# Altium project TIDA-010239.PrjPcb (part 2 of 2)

## Sheet TIDA-010239_Relay_DRV.SchDoc
size 431 x 279 mm; Date: Not shown in title block; ApprovedBy: Not shown in title block; CheckedBy: Not shown in title block; Author: Not shown in title block; CompanyName: Not shown in title block; Engineer: Not shown in title block; Organization: Not shown in title block; Address1: Not shown in title block; Address2: Not shown in title block; Address3: Not shown in title block; Address4: Not shown in title block; DocumentNumber: 1; Revision: Use project parameter SCH_Rev; SheetNumber: 4; SheetTotal: 9; PageSetup: Record=PageOptions¦CenterHorizontal=True¦CenterVertical=True¦PrintScale=1.00¦XCorrection=1.00¦YCorrection=1.00¦PrintKind=0¦BorderSize=5000000¦LeftOffset=0¦BottomOffset=0¦Orientation=2¦PaperLength=1000¦PaperWidth=1000¦Scale=100¦PaperSource=15¦PrintQuality=600¦MediaType=1¦DitherType=10¦PaperKind=Letter¦PrintScaleMode=1
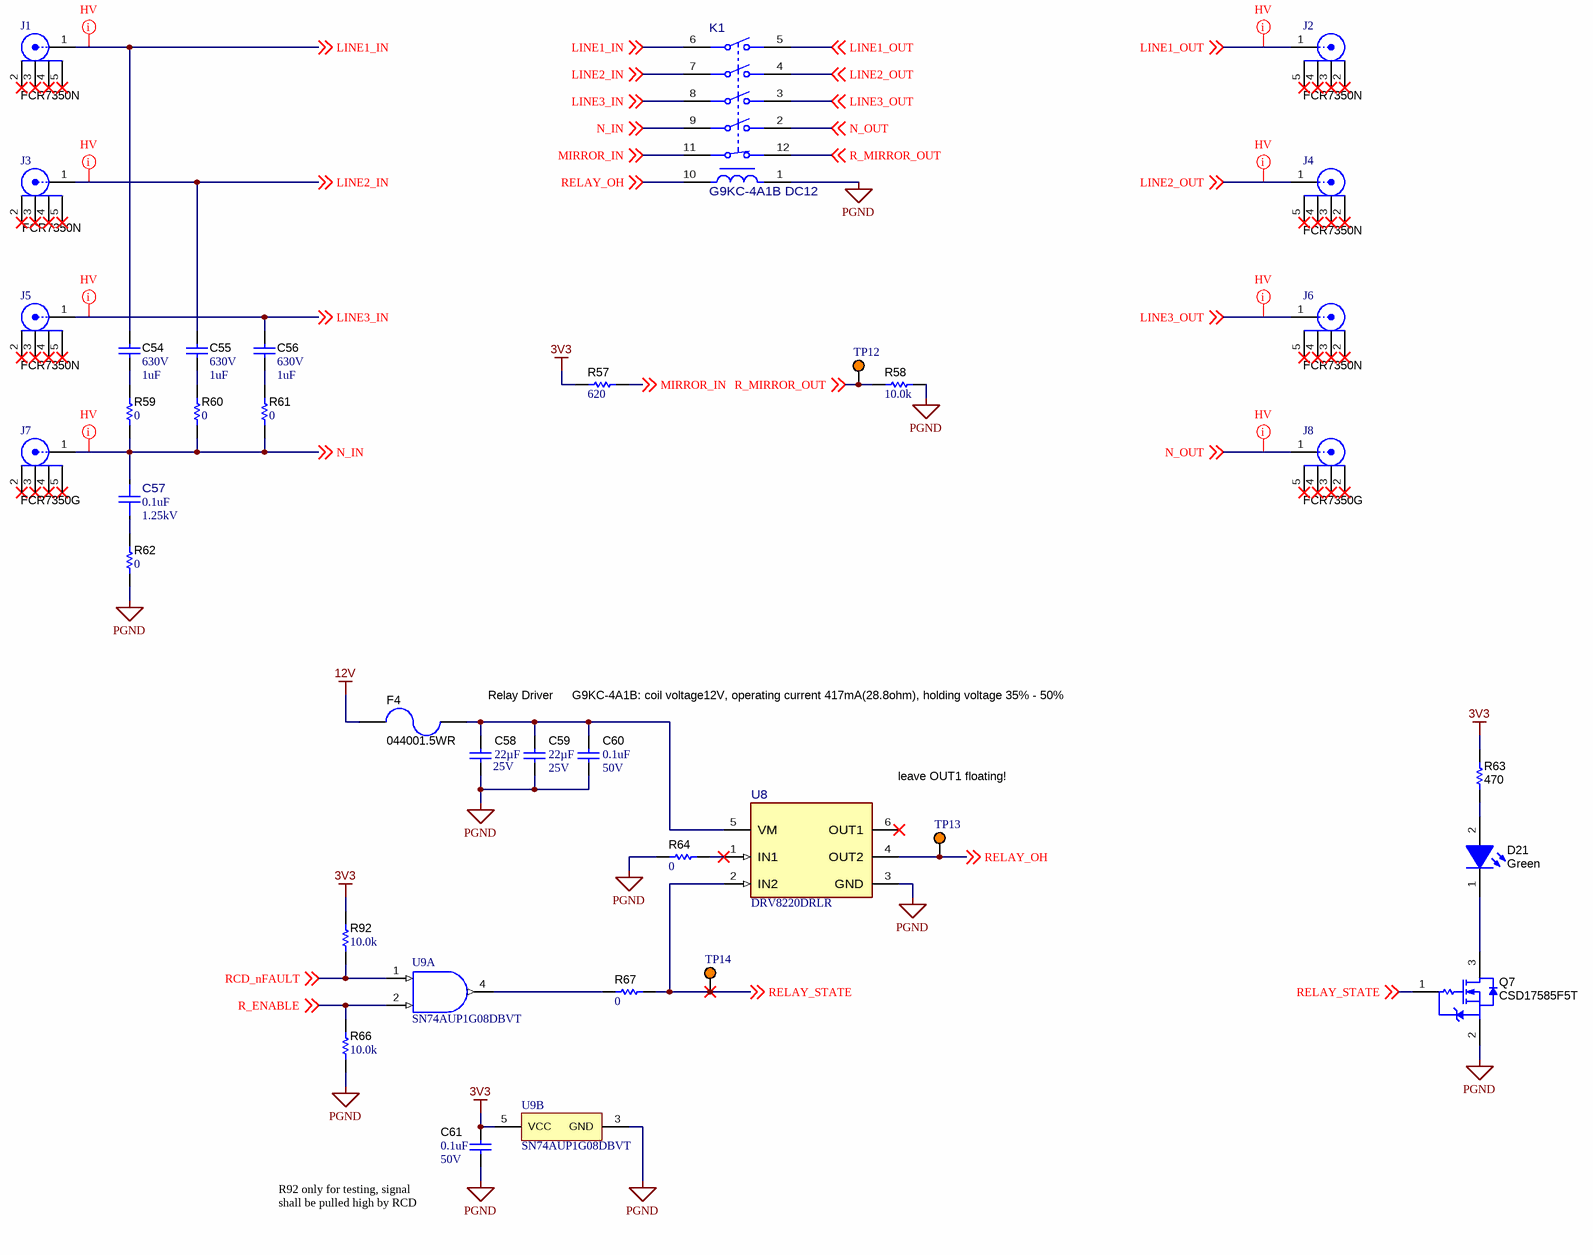
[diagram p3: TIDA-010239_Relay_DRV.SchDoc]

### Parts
C54  VDC_V: 630V  ValueDisplayed: 1uF  [B32923_20.5mm]  (hidden comment: B32923C3105M)
C55  VDC_V: 630V  ValueDisplayed: 1uF  [B32923_20.5mm]  (hidden comment: B32923C3105M)
C56  VDC_V: 630V  ValueDisplayed: 1uF  [B32923_20.5mm]  (hidden comment: B32923C3105M)
C57  ValueDisplayed: 0.1uF  VDC_V: 1.25kV  [FP-PHE850ED6100MD18R06L2_RADIAL-MFG]  (hidden comment: PHE850ED6100MD18R06L2)
C58  VDC_V: 25V  ValueDisplayed: 22µF  [1210_270]  (hidden comment: CC1210KKX7R8BB226)
C59  VDC_V: 25V  ValueDisplayed: 22µF  [1210_270]  (hidden comment: CC1210KKX7R8BB226)
C60  value 0.1uF  VDC_V: 50V  [0603]  (hidden comment: C1608X7R1H104K080AA)
C61  value 0.1uF  VDC_V: 50V  [0603]  (hidden comment: C1608X7R1H104K080AA)
D21  value Green  [WL-SMCW_GREEN]  (hidden comment: 150060GS75000)
F4  044001.5WR  [1206]
J1  FCR7350N  [FP-FCR7350N_CONN_BANANA_JACK-MFG]
J2  FCR7350N  [FP-FCR7350N_CONN_BANANA_JACK-MFG]
J3  FCR7350N  [FP-FCR7350N_CONN_BANANA_JACK-MFG]
J4  FCR7350N  [FP-FCR7350N_CONN_BANANA_JACK-MFG]
J5  FCR7350N  [FP-FCR7350N_CONN_BANANA_JACK-MFG]
J6  FCR7350N  [FP-FCR7350N_CONN_BANANA_JACK-MFG]
J7  FCR7350G  [FP-FCR7350G_CONN_BANANA_JACK-MFG]
J8  FCR7350G  [FP-FCR7350G_CONN_BANANA_JACK-MFG]
K1  G9KC-4A1B DC12  [FP-G9KC-4A1B DC12_PTH_RELAY_58MM0_35MM0-MFG]
Q7  CSD17585F5T  [YJK0003A]
R57  ValueDisplayed: 620  [0603]  (hidden comment: RC0603FR-07620RL)
R58  ValueDisplayed: 10.0k  [0603]  (hidden comment: RC0603FR-0710KL)
R59  ValueDisplayed: 0  [1206]  (hidden comment: RC1206JR-070RL)
R60  ValueDisplayed: 0  [1206]  (hidden comment: RC1206JR-070RL)
R61  ValueDisplayed: 0  [1206]  (hidden comment: RC1206JR-070RL)
R62  ValueDisplayed: 0  [1206]  (hidden comment: RC1206JR-070RL)
R63  ValueDisplayed: 470  [0402]  (hidden comment: RC0402FR-07470RL)
R64  ValueDisplayed: 0  [0603]  (hidden comment: RCS06030000Z0EA)
R66  ValueDisplayed: 10.0k  [0603]  (hidden comment: RC0603FR-0710KL)
R67  ValueDisplayed: 0  [0603]  (hidden comment: RCS06030000Z0EA)
R92  ValueDisplayed: 10.0k  [0603]  (hidden comment: RC0603FR-0710KL)
TP12  5003  [Keystone5003]  (value not drawn)
TP13  5003  [Keystone5003]  (value not drawn)
TP14  5003  [Keystone5003]  (value not drawn)
U8  DRV8220DRLR  [DRL0006A-MFG]
U9  SN74AUP1G08DBVT  [DBV0005A_N]  (parts A,B of 2)

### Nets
3V3: C61.1 R57.1 R63.2 R92.2 U9.5(VCC)
12V: F4.2
PGND: C58.1 C59.1 C60.2 C61.2 K1.1 Q7.2(S) R58.2 R62.1 R64.2 R66.1 U8.3(GND) U9.3(GND)
LINE1_IN: C54.1 J1.1 K1.6 ; off-sheet LINE1_IN
LINE1_OUT: J2.1 K1.5 ; off-sheet LINE1_OUT
LINE2_IN: C55.1 J3.1 K1.7 ; off-sheet LINE2_IN
LINE2_OUT: J4.1 K1.4 ; off-sheet LINE2_OUT
LINE3_IN: C56.1 J5.1 K1.8 ; off-sheet LINE3_IN
LINE3_OUT: J6.1 K1.3 ; off-sheet LINE3_OUT
MIRROR_IN: K1.11 R57.2 ; off-sheet MIRROR_IN
N_IN: C57.2 J7.1 K1.9 R59.1 R60.1 R61.1 ; off-sheet N_IN
N_OUT: J8.1 K1.2 ; off-sheet N_OUT
R_ENABLE: R66.2 U9.2(B) ; off-sheet R_ENABLE
R_MIRROR_OUT: K1.12 R58.1 TP12.1 ; off-sheet R_MIRROR_OUT
RCD_nFAULT: R92.1 U9.1(A) ; off-sheet RCD_nFAULT
RELAY_OH: K1.10 TP13.1 U8.4(OUT2) ; off-sheet RELAY_OH
RELAY_STATE: Q7.1(G) R67.2 TP14.1 U8.2(IN2) ; off-sheet RELAY_STATE
NetC54_2: C54.2 R59.2
NetC55_2: C55.2 R60.2
NetC56_2: C56.2 R61.2
NetC57_1: C57.1 R62.2
NetC58_2: C58.2 C59.2 C60.1 F4.1 U8.5(VM)
NetD21_1: D21.1(K) Q7.3(D)
NetD21_2: D21.2(A) R63.1
NetR64_1: R64.1 U8.1(IN1)
NetR67_1: R67.1 U9.4(Y)

Not connected (* = marked no-connect by the designer): J1 2* 3* 4* 5*; J2 2* 3* 4* 5*; J3 2* 3* 4* 5*; J4 2* 3* 4* 5*; J5 2* 3* 4* 5*; J6 2* 3* 4* 5*; J7 2* 3* 4* 5*; J8 2* 3* 4* 5*; U8 6(OUT1)*

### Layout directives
net class HV: LINE1_IN, LINE1_OUT, LINE2_IN, LINE2_OUT, LINE3_IN, LINE3_OUT, N_IN, N_OUT

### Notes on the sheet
- Relay Driver
- G9KC-4A1B: coil voltage12V, operating current 417mA(28.8ohm), holding voltage 35% - 50%
- leave OUT1 floating!
- R92 only for testing, signal shall be pulled high by RCD

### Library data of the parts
C54-C56 = CMP-0012419-3: CAP, Film, 1 uF, 630 V, +/- 20%, 0.018 ohm, TH; Manufacturer: TDK; ESR_ohm: 18m; Polarized: N; SizeAreaWB_mm2: 370.5; Value: 1uF; TaMax_C: 110°C; SizeZ_mm: 20.5; SizeX_mm: 11; SizeY_mm: 26.5; SizeArea_mm2: 291.5; Cap_F: 1µF; IRMS_A: 97mA; AEC Category: Q200
C57 = CMP-0040174-1: Cap Film Suppression Y2 0.1uF 1250VDC/300VAC PP 20% (26 X 10.5 X 19mm) Radial 22.5mm 110C Tray; Manufacturer: Kemet; AEC Qualified: No; Cap_F: 100nF; VAC: 300V; Value: 100nF
C58 C59 = CMP-0082267-1: CAP, CERM, 22 µF, 25 V,+/- 10%, X7R, 1210; Manufacturer: Yageo; TaMin_C: -55°C; ESR_ohm: 1m; Polarized: N; SizeAreaWB_mm2: 14.7; Value1: 0.001 ohm; U/M: EA; Value: 22uF; TaMax_C: 125°C; SizeZ_mm: 2.7; SizeX_mm: 3.2; SizeY_mm: 2.5; Cap_Case: 1210; SizeArea_mm2: 8; AEC Category: Q200
C60 C61 = CMP-0007044-5: CAP, CERM, 0.1 uF, 50 V, +/- 10%, X7R, 0603; Manufacturer: TDK; TaMin_C: -55°C; ESR_ohm: 29.6m; Polarized: N; SizeAreaWB_mm2: 4.68; Value1: 0.0296 ohm; U/M: EA; TaMax_C: 125°C; SizeZ_mm: 1; SizeX_mm: 1.6; SizeY_mm: 0.8; SizeArea_mm2: 1.28; Cap_F: 100nF; IRMS_A: 971.99mA; AEC Category: Q200
D21 = CMP-0002905-2: LED, Green, SMD; Manufacturer: Wurth Elektronik; Type: InGaN; Vf_V: 3.2V; Io_A: 20mA; Tjmax_C: 85°C; Value1: W; Angle: 140
F4 = CMP-0003461-2: Fuse, 1.5 A, 50VAC/VDC, SMD; Manufacturer: Littelfuse; Irating_A: 1.5A; SizeAreaWB_mm2: 10.92; Interrupt_AC: 50A; VAC_V: 50V; SizeZ_mm: 1.35; SizeX_mm: 3.2; SizeY_mm: 1.6; SizeArea_mm2: 5.12; Rtyp_Ohm: 0.1759; MeltingTyp: 0.50652
J1-J6 = CMP-0098296-2: Banana Test Connector, Socket, PCB Mount, 24 A, 1 kV, Gold Plated Contacts, Brown; Manufacturer: CLIFF Electronic Components; Current_A: 24A; Voltage_V: 1kV; AEC Qualified: No; Conn Orientation: Right Angle; Is Female: yes; SizeZ_mm: 11.6mm; Standoff Height: 0.7mm
J7 J8 = CMP-0098294-2: Banana Test Connector, Socket, PCB Mount, 24 A, 1 kV, Gold Plated Contacts, Green; Manufacturer: CLIFF Electronic Components; Current_A: 24A; Voltage_V: 1kV; AEC Qualified: No; Conn Orientation: Right Angle; SizeZ_mm: 11.6mm; Standoff Height: 0.7mm
K1 = CMP-0127083-1: General Purpose Relay 5PST-4NO/1NC (4 Form A, 1 Form B) 12VDC Coil Through Hole; Manufacturer: Omron; Coil Current_A: 417mA; Coil Power_W: 5W; Coil Type: Non-Latching; Coil Voltage_VDC: 12V; Contact Form: 5PST-4NO-1NC; Contact Rating_A: 40A; SizeZ_mm: 47.5mm; AEC Qualified: No; Coil Resistance: 28.8Ω; TaMax_C: +85°C; TaMin_C: -40°C
Q7 = CMP-0067551-1: MOSFET, N-CH, 30 V, 5.9 A, YJK0003A (PICOSTAR-3); Alternate Manufacturer: None; Manufacturer: Texas Instruments; Rdson45_ohm: 0.033; QgTyp_nC: 1.9; SizeAreaWB_mm2: 4.3077; Vgs_V: 20V; Value1: 0.033 ohm; VdsMax_V: 30V; U/M: EA; Value: 30V; IdsMax_A: 5.9A; SizeZ_mm: 0.35; SizeX_mm: 1.49; SizeY_mm: 0.73; Value2: 1.9 nC; SizeArea_mm2: 1.0877; ChType: N; AEC Category: Q101
R57 = CMP-0023219-5: RES, 620, 1%, 0.1 W, 0603; Manufacturer: Yageo; Power_W: 100mW; TempCo: 100 ppm/C; Value_Code: 620R; Value: 620; SizeX_mm: 1.6; SizeY_mm: 0.8; SizeZ_mm: 1; Value2: 0.1W; SizeArea_mm2: 1.28; AEC Qualified: N; VDC_V: 75V; AEC Category: Q200; SizeAreaWB_mm2: 4.68
R58 R66 R92 = CMP-0022746-5: RES, 10.0 k, 1%, 0.1 W, 0603; Manufacturer: Yageo; Power_W: 100mW; TempCo: 100 ppm/C; Value_Code: 10k0; Value: 10.0k; EIA_Code: E96; Res_ohm: 10k; SizeX_mm: 1.6; SizeY_mm: 0.8; SizeZ_mm: 1; Value2: 0.1W; SizeArea_mm2: 1.28; AEC Qualified: N; VDC_V: 75V; AEC Category: Q200; SizeAreaWB_mm2: 4.68
R59-R62 = CMP-0018759-2: RES, 0, 5%, 0.25 W, 1206; Manufacturer: Yageo America; Power_W: 250mW; TempCo: 200 ppm/C; Value_Code: 0000; U/M: EA; Value: 0; EIA_Code: E24; SizeX_mm: 3.2; SizeY_mm: 1.6; SizeZ_mm: 1.35; Value2: 0.25W; SizeArea_mm2: 5.12; VDC_V: 200V; AEC Category: Q200
R63 = CMP-0026736-1: RES, 470, 1%, 0.063 W, 0402; Manufacturer: Yageo America; Power_W: 63mW; TempCo: 100 ppm/C; Value_Code: 470R; U/M: EA; Value: 470; SizeX_mm: 1; SizeY_mm: 0.5; SizeZ_mm: 0.6; Value2: 0.063W; AEC Qualified: N; VDC_V: 50V; AEC Category: Q200
R64 R67 = CMP-0081973-1: RES, 0, 0%, 0.25 W, AEC-Q200 Grade 0, 0603; Manufacturer: Vishay-Dale; SizeAreaWB_mm2: 4.68; SizeArea_mm2: 1.28; AEC Qualified: Y; AEC Category: Q200; Value: 0; SizeZ_mm: 1; SizeY_mm: 0.8; Power_W: 250mW; Value2: 0.25W; SizeX_mm: 1.6
TP12-TP14 = CMP-0055140-2: Test Point, Miniature, Orange, TH; Manufacturer: Keystone Electronics; CNHeader: FALSE; Green_Lifecycle: Active; Green_REACh: Passed; ContactFinish: Silver; CT: TRUE
U8 = CMP-0090278-3: 18V, 1A H-bridge motor driver, PWM, PH/EN, ½ bridge control, with low power sleep mode; Manufacturer: Texas Instruments; Standoff Height: 0mm; TaMax_C: +125°C; Number Of Outputs: 2; AEC Qualified: No; TJmax_C: +150°C; SizeZ_mm: 0.6mm; AEC Category: Q200; TaMin_C: -40°C; Switching Frequency: 100kHz; Min Supply Voltage: 4.5V; Motor Type: Brushed; CompType: IC
U9 = CMP-0051576-2: Low-Power Single 2-Input Positive-AND Gate, DBV0005A (SOT-23-5); Manufacturer: Texas Instruments; 3-State Output: No; Output Type: CMOS; F @ Nom Voltage(Max)(Mhz): 100; Rating: Catalog; Voltage(Nom)(V): 0.8,1.2,1.5,1.8,2.5,3.3; Logic: True; Output Drive (IOL/IOH)(Max)(mA): 20/-20; tpd @ Nom Voltage(Max)(ns): 32.8,20.9,14.2,11,7.6,6.2; Bits(#): 1; ICC @ Nom Voltage(Max)(mA): 0.0009; Gate Type: AND; VCC(Max)(V): 3.6; VCC(Min)(V): 0.8; AEC Category: Q200; AEC Qualified: N; CompType: IC; SizeAreaWB_mm2: 14.82; SizeArea_mm2: 8.12; SizeX_mm: 2.8; SizeY_mm: 2.9; SizeZ_mm: 1.45

## Sheet TIDA-010239_Weld_Detection.SchDoc
size 431 x 279 mm; Date: Not shown in title block; ApprovedBy: Not shown in title block; CheckedBy: Not shown in title block; Author: Not shown in title block; CompanyName: Not shown in title block; Engineer: Not shown in title block; Organization: Not shown in title block; Address1: Not shown in title block; Address2: Not shown in title block; Address3: Not shown in title block; Address4: Not shown in title block; DocumentNumber: 1; Revision: Use project parameter SCH_Rev; SheetNumber: 5; SheetTotal: 9; PageSetup: Record=PageOptions¦CenterHorizontal=True¦CenterVertical=True¦PrintScale=1.00¦XCorrection=1.00¦YCorrection=1.00¦PrintKind=0¦BorderSize=5000000¦LeftOffset=0¦BottomOffset=0¦Orientation=2¦PaperLength=1000¦PaperWidth=1000¦Scale=100¦PaperSource=15¦PrintQuality=600¦MediaType=1¦DitherType=10¦PaperKind=Letter¦PrintScaleMode=1
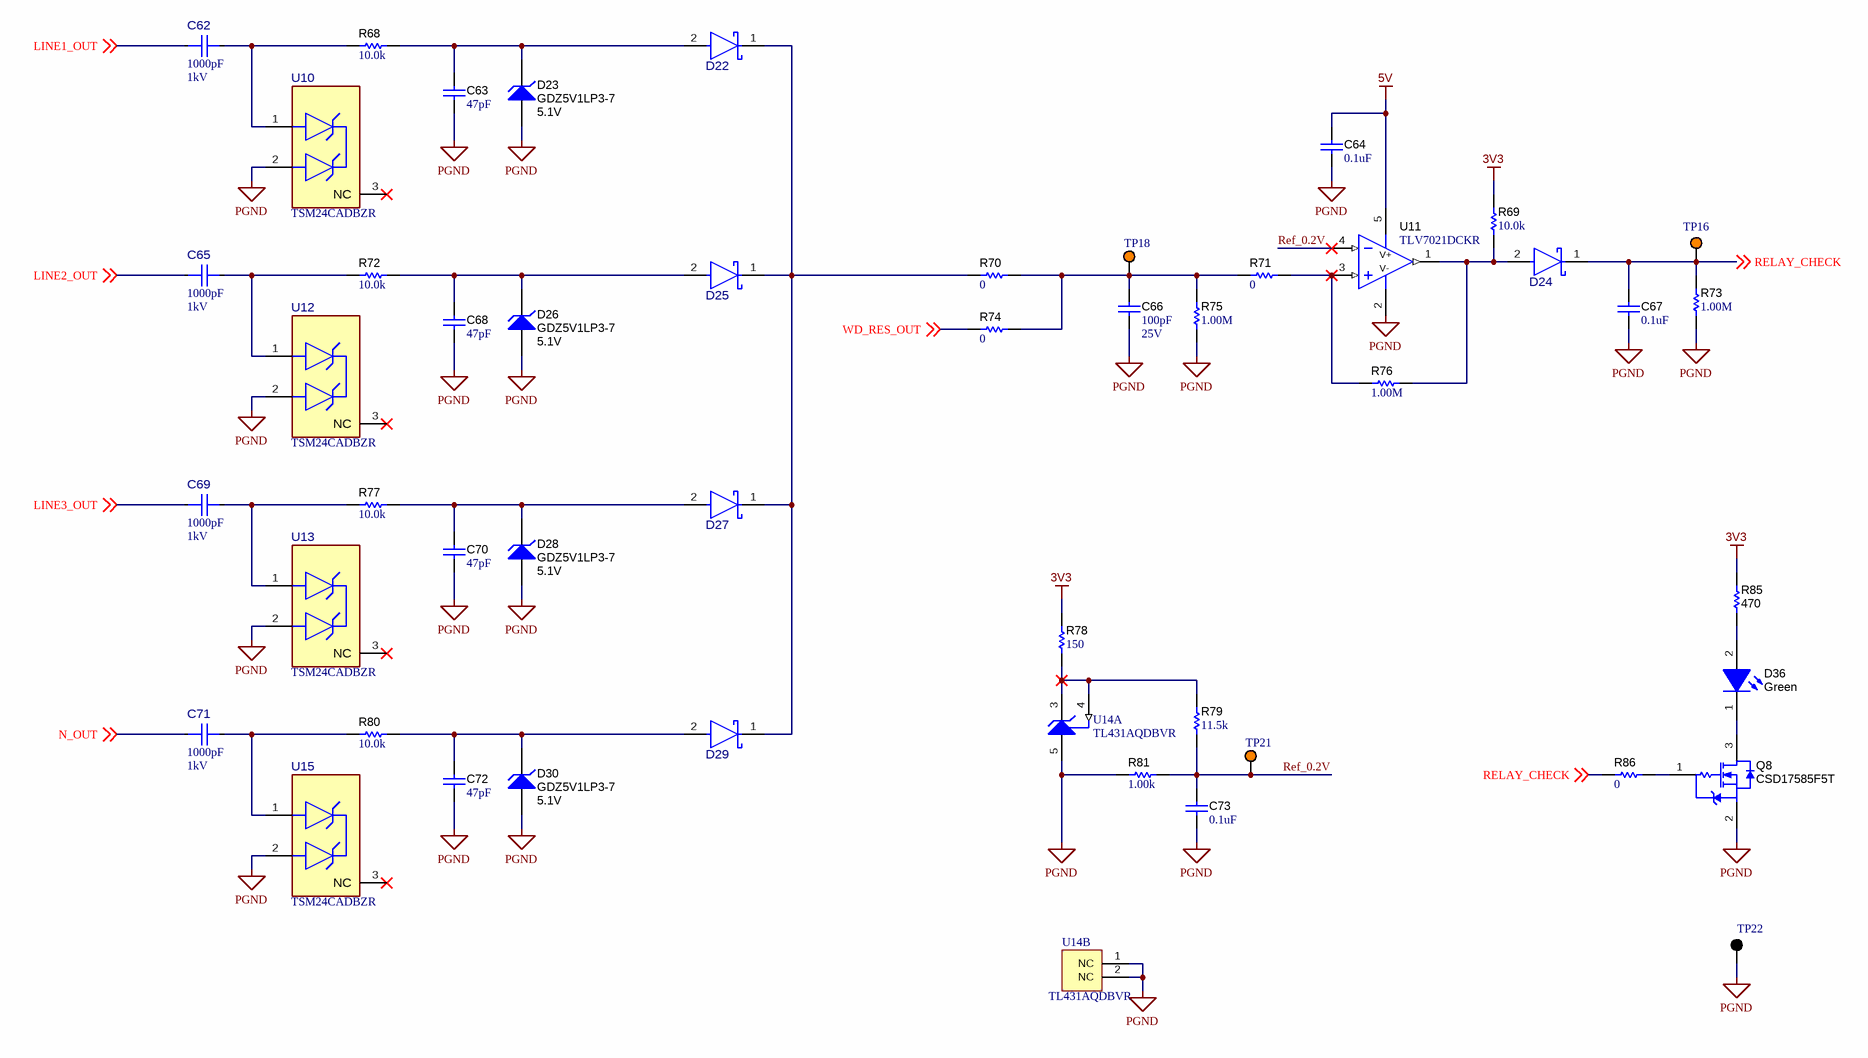
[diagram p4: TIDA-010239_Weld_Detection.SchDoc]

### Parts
C62  ValueDisplayed: 1000pF  VDC_V: 1kV  [FP-VY2102M29Y5US6TV7_RADIAL-MFG]  (hidden comment: VY2102M29Y5US6TV7)
C63  ValueDisplayed: 47pF  [0603]  (hidden comment: C0603C470J1GACAUTO)
C64  value 0.1uF  [0603]  (hidden comment: C1608X7R1H104K080AA)
C65  ValueDisplayed: 1000pF  VDC_V: 1kV  [FP-VY2102M29Y5US6TV7_RADIAL-MFG]  (hidden comment: VY2102M29Y5US6TV7)
C66  Cap_F: 100pF  VDC_V: 25V  [0603S]  (hidden comment: 06033C101KAT2A)
C67  value 0.1uF  [0603]  (hidden comment: C1608X7R1H104K080AA)
C68  ValueDisplayed: 47pF  [0603]  (hidden comment: C0603C470J1GACAUTO)
C69  ValueDisplayed: 1000pF  VDC_V: 1kV  [FP-VY2102M29Y5US6TV7_RADIAL-MFG]  (hidden comment: VY2102M29Y5US6TV7)
C70  ValueDisplayed: 47pF  [0603]  (hidden comment: C0603C470J1GACAUTO)
C71  ValueDisplayed: 1000pF  VDC_V: 1kV  [FP-VY2102M29Y5US6TV7_RADIAL-MFG]  (hidden comment: VY2102M29Y5US6TV7)
C72  ValueDisplayed: 47pF  [0603]  (hidden comment: C0603C470J1GACAUTO)
C73  value 0.1uF  [0603]  (hidden comment: C1608X7R1H104K080AA)
D22  GSRB751S-40  [FP-GSRB751S-40_SOD523-0]  (value not drawn)
D23  GDZ5V1LP3-7  value 5.1V  [X3-DFN0603-2]
D24  GSRB751S-40  [FP-GSRB751S-40_SOD523-0]  (value not drawn)
D25  GSRB751S-40  [FP-GSRB751S-40_SOD523-0]  (value not drawn)
D26  GDZ5V1LP3-7  value 5.1V  [X3-DFN0603-2]
D27  GSRB751S-40  [FP-GSRB751S-40_SOD523-0]  (value not drawn)
D28  GDZ5V1LP3-7  value 5.1V  [X3-DFN0603-2]
D29  GSRB751S-40  [FP-GSRB751S-40_SOD523-0]  (value not drawn)
D30  GDZ5V1LP3-7  value 5.1V  [X3-DFN0603-2]
D36  value Green  [WL-SMCW_GREEN]  (hidden comment: 150060GS75000)
Q8  CSD17585F5T  [YJK0003A]
R68  ValueDisplayed: 10.0k  [0603]  (hidden comment: RC0603FR-0710KL)
R69  ValueDisplayed: 10.0k  [0603]  (hidden comment: RC0603FR-0710KL)
R70  ValueDisplayed: 0  [0603]  (hidden comment: RCS06030000Z0EA)
R71  ValueDisplayed: 0  [0603]  (hidden comment: RCS06030000Z0EA)
R72  ValueDisplayed: 10.0k  [0603]  (hidden comment: RC0603FR-0710KL)
R73  ValueDisplayed: 1.00M  [0603]  (hidden comment: RC0603FR-071ML)
R74  ValueDisplayed: 0  [0603]  (hidden comment: RCS06030000Z0EA)
R75  ValueDisplayed: 1.00M  [0603]  (hidden comment: RC0603FR-071ML)
R76  ValueDisplayed: 1.00M  [0603]  (hidden comment: RC0603FR-071ML)
R77  ValueDisplayed: 10.0k  [0603]  (hidden comment: RC0603FR-0710KL)
R78  ValueDisplayed: 150  [0603]  (hidden comment: RC0603FR-07150RL)
R79  ValueDisplayed: 11.5k  [0603]  (hidden comment: RC0603FR-0711K5L)
R80  ValueDisplayed: 10.0k  [0603]  (hidden comment: RC0603FR-0710KL)
R81  ValueDisplayed: 1.00k  [0603]  (hidden comment: CRCW06031K00FKEA)
R85  ValueDisplayed: 470  [0402]  (hidden comment: RC0402FR-07470RL)
R86  ValueDisplayed: 0  [0603]  (hidden comment: RCS06030000Z0EA)
TP16  5003  [Keystone5003]  (value not drawn)
TP18  5003  [Keystone5003]  (value not drawn)
TP21  5003  [Keystone5003]  (value not drawn)
TP22  5011  [Keystone5011]  (value not drawn)
U10  TSM24CADBZR  [DBZ0003A-MFG]
U11  TLV7021DCKR  [DCK0005A_N]
U12  TSM24CADBZR  [DBZ0003A-MFG]
U13  TSM24CADBZR  [DBZ0003A-MFG]
U14  TL431AQDBVR  [DBV0005A_N]  (parts A,B of 2)
U15  TSM24CADBZR  [DBZ0003A-MFG]

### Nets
3V3: R69.2 R78.2 R85.2
5V: C64.1 U11.5(V+)
PGND: C63.2 C64.2 C66.2 C67.2 C68.2 C70.2 C72.2 C73.2 D23.2(A) D26.2(A) D28.2(A) D30.2(A) Q8.2(S) R73.1 R75.1 R81.1 TP22.1 U10.2(2_IO) U11.2(V-) U12.2(2_IO) U13.2(2_IO) U14.1(NC) U14.2(NC) U14.5(ANODE) U15.2(2_IO)
LINE1_OUT: C62.1 ; off-sheet LINE1_OUT
LINE2_OUT: C65.1 ; off-sheet LINE2_OUT
LINE3_OUT: C69.1 ; off-sheet LINE3_OUT
N_OUT: C71.1 ; off-sheet N_OUT
Ref_0.2V: C73.1 R79.1 R81.2 TP21.1 U11.4(IN-)
RELAY_CHECK: C67.1 D24.1(CATHODE) R73.2 R86.1 TP16.1 ; off-sheet RELAY_CHECK
WD_RES_OUT: R74.1 ; off-sheet WD_RES_OUT
NetC62_2: C62.2 R68.1 U10.1(1_IO)
NetC63_1: C63.1 D22.2(ANODE) D23.1(K) R68.2
NetC65_2: C65.2 R72.1 U12.1(1_IO)
NetC66_1: C66.1 R70.2 R71.1 R74.2 R75.2 TP18.1
NetC68_1: C68.1 D25.2(ANODE) D26.1(K) R72.2
NetC69_2: C69.2 R77.1 U13.1(1_IO)
NetC70_1: C70.1 D27.2(ANODE) D28.1(K) R77.2
NetC71_2: C71.2 R80.1 U15.1(1_IO)
NetC72_1: C72.1 D29.2(ANODE) D30.1(K) R80.2
NetD22_1: D22.1(CATHODE) D25.1(CATHODE) D27.1(CATHODE) D29.1(CATHODE) R70.1
NetD24_2: D24.2(ANODE) R69.1 R76.1 U11.1(OUT)
NetD36_1: D36.1(K) Q8.3(D)
NetD36_2: D36.2(A) R85.1
NetQ8_1: Q8.1(G) R86.2
NetR71_2: R71.2 R76.2 U11.3(IN+)
NetR78_1: R78.1 R79.2 U14.3(CATHODE) U14.4(REF)

Not connected (* = marked no-connect by the designer): U10 3(NC)*; U12 3(NC)*; U13 3(NC)*; U15 3(NC)*

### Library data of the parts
C62 C65 C69 C71 = CMP-0120129-1: 1000 pF ±20% 440VAC Ceramic Capacitor Y5U (E) Radial, Disc; Manufacturer: Vishay; AEC Qualified: No; Cap_F: 1nF; SizeZ_mm: 11.5mm; TempCo: +22/-56%; VAC_X: 440V; VAC_Y: 300V; Value: 1nF
C63 C68 C70 C72 = CMP-0085572-1: CAP, CERM, 47 pF, 100 V,+/- 5%, C0G/NP0, AEC-Q200 Grade 1, 0603; Manufacturer: Kemet; TaMax_C: 125°C; AEC Category: Q200; AEC Grade: 1; VDC_V: 100V; TaMin_C: -55°C; SizeArea_mm2: 1.28; Value: 47pF; AEC Qualified: Y; Polarized: N; SizeX_mm: 1.6; U/M: EA; SizeY_mm: 0.8; SizeAreaWB_mm2: 4.68
C64 C67 C73 = CMP-0007044-5: CAP, CERM, 0.1 uF, 50 V, +/- 10%, X7R, 0603; Manufacturer: TDK; TaMin_C: -55°C; ESR_ohm: 29.6m; Polarized: N; SizeAreaWB_mm2: 4.68; Value1: 0.0296 ohm; U/M: EA; TaMax_C: 125°C; SizeZ_mm: 1; SizeX_mm: 1.6; SizeY_mm: 0.8; Value2: 50V; SizeArea_mm2: 1.28; Cap_F: 100nF; IRMS_A: 971.99mA; AEC Category: Q200
C66 = CMP-0006751-4: CAP, CERM, 100 pF, 25 V, +/- 10%, X7R, 0603; Manufacturer: AVX; TaMin_C: -55°C; Polarized: N; SizeAreaWB_mm2: 4.68; Value1: Unknown; U/M: EA; Value: 100pF; TaMax_C: 125°C; SizeZ_mm: 1; SizeX_mm: 1.6; SizeY_mm: 0.8; Cap_Case: 0603; SizeArea_mm2: 1.28; AEC Category: Q200
D22 D24 D25 D27 D29 = CMP-0120115-1: Diode 30 V 30mA Surface Mount SOD-523; Manufacturer: Good-Ark; AEC Qualified: No; SizeZ_mm: 0.77mm; TJmax_C: 125°C; Vf_V: 40V; Vr_V: 30V; Cap_F: 2pF; Max Surge Forward Current: 200mA; Peak Reverse Current: 0.5uA; Standoff Height: 0.01mm
D23 D26 D28 D30 = CMP-0006072-3: Diode, Zener, 5.1 V, 250 mW, 2-XFDFN; Manufacturer: Diodes Inc.; Value1: 0.25W; Power_W: 250mW; RJA_CperW: 500; AEC Category: Q101
D36 = CMP-0002905-2: as D21 on sheet TIDA-010239_Relay_DRV
Q8 = CMP-0067551-1: as Q7 on sheet TIDA-010239_Relay_DRV
R68 R69 R72 R77 R80 = CMP-0022746-5: as R58 on sheet TIDA-010239_Relay_DRV
R70 R71 R74 R86 = CMP-0081973-1: as R64 on sheet TIDA-010239_Relay_DRV
R73 R75 R76 = CMP-0022899-4: RES, 1.00 M, 1%, 0.1 W, 0603; Manufacturer: Yageo; Power_W: 100mW; TempCo: 100 ppm/C; Value_Code: 1M00; Value: 1.00Meg; EIA_Code: E96; Res_ohm: 1M; SizeX_mm: 1.6; SizeY_mm: 0.8; SizeZ_mm: 1; Value2: 0.1W; SizeArea_mm2: 1.28; AEC Qualified: N; VDC_V: 75V; AEC Category: Q200; SizeAreaWB_mm2: 4.68
R78 = CMP-0022809-5: RES, 150, 1%, 0.1 W, 0603; Manufacturer: Yageo; Power_W: 100mW; TempCo: 100 ppm/C; Value_Code: 150R; Value: 150; EIA_Code: E96; SizeX_mm: 1.6; SizeY_mm: 0.8; SizeZ_mm: 1; Value2: 0.1W; SizeArea_mm2: 1.28; AEC Qualified: N; VDC_V: 75V; AEC Category: Q200; SizeAreaWB_mm2: 4.68
R79 = CMP-0022761-5: RES, 11.5 k, 1%, 0.1 W, 0603; Manufacturer: Yageo; Power_W: 100mW; TempCo: 100 ppm/C; Value_Code: 11k5; Value: 11.5k; EIA_Code: E96; SizeX_mm: 1.6; SizeY_mm: 0.8; SizeZ_mm: 1; Value2: 0.1W; SizeArea_mm2: 1.28; AEC Qualified: N; VDC_V: 75V; AEC Category: Q200; SizeAreaWB_mm2: 4.68
R81 = CMP-0022109-5: RES, 1.00 k, 1%, 0.1 W, AEC-Q200 Grade 0, 0603; Manufacturer: Vishay-Dale; Power_W: 100mW; TempCo: 100 ppm/C; Value_Code: 1k00; Value: 1.00k; EIA_Code: E96; Res_ohm: 1k; SizeX_mm: 1.6; SizeY_mm: 0.8; SizeZ_mm: 1; Value2: 0.1W; SizeArea_mm2: 1.28; AEC Qualified: Y; VDC_V: 75V; AEC Category: Q200; AEC Grade: 0
R85 = CMP-0026736-1: as R63 on sheet TIDA-010239_Relay_DRV
TP16 TP18 TP21 = CMP-0055140-2: as TP12-TP14 on sheet TIDA-010239_Relay_DRV
TP22 = CMP-0055148-2: Test Point, Multipurpose, Black, TH; Manufacturer: Keystone Electronics; CNHeader: FALSE; ContactFinish: Silver; Green_REACh: Passed; Green_Lifecycle: Active; CT: TRUE
U10 U12 U13 U15 = CMP-0120116-1: ±24 V Low Capacitance Surge Diode for Industrial Networks in SOT-23 Package; Manufacturer: Texas Instruments; SizeZ_mm: 1.12mm; AEC Qualified: No; Breakdown Voltage: 25.5V; Cap_F: 14pF; Clamping Voltage: 35V; Direction: Bidirectional; Ipp: 30A; Number Of Channels: 1; Ppk: 1200W; Standoff Height: 0.01mm; TaMax_C: +125°C; TaMin_C: -40°C; VRWM: 24V
U11 = CMP-0085889-2: Small-Size Micropower Low-Voltage Comparator, DCK0005A (SOT-SC70-5); Manufacturer: Texas Instruments; Alternate PartNumber: TLV7021DCKT; SizeAreaWB_mm2: 9.3; SizeY_mm: 2; Rating: Catalog; SizeZ_mm: 1.1; SizeX_mm: 2.1; CompType: IC; AEC Qualified: N; SizeArea_mm2: 4.2; AEC Category: Q200
U14 = CMP-0032940-1: Adjustable Precision Shunt Regulator, 34 ppm / degC, 100 mA, -40 to 125 degC, 5-pin SOT-23 (DBV), Green (RoHS & no Sb/Br); Manufacturer: Texas Instruments; Min Iz for Regulation(uA): 600; Rating: Catalog; SubFamily: Shunt Voltage Reference; Temp Coeff(Typ)(ppm/ degree C): 34; Iout/Iz(Max)(mA): 100; Temp Coeff(Max)(ppm/ degree C): 92; VO Adj(Min)(V): 2.495; VO Adj(Max)(V): 36; Initial Accuracy @ 25/deg C(%): 1

## Sheet TIDA-010239_Weld_Detection_B.SchDoc
size 431 x 279 mm; Date: Not shown in title block; ApprovedBy: Not shown in title block; CheckedBy: Not shown in title block; Author: Not shown in title block; CompanyName: Not shown in title block; Engineer: Not shown in title block; Organization: Not shown in title block; Address1: Not shown in title block; Address2: Not shown in title block; Address3: Not shown in title block; Address4: Not shown in title block; DocumentNumber: 1; Revision: Use project parameter SCH_Rev; SheetNumber: 6; SheetTotal: 9; PageSetup: Record=PageOptions¦CenterHorizontal=True¦CenterVertical=True¦PrintScale=1.00¦XCorrection=1.00¦YCorrection=1.00¦PrintKind=0¦BorderSize=5000000¦LeftOffset=0¦BottomOffset=0¦Orientation=2¦PaperLength=1000¦PaperWidth=1000¦Scale=100¦PaperSource=15¦PrintQuality=600¦MediaType=1¦DitherType=10¦PaperKind=Letter¦PrintScaleMode=1
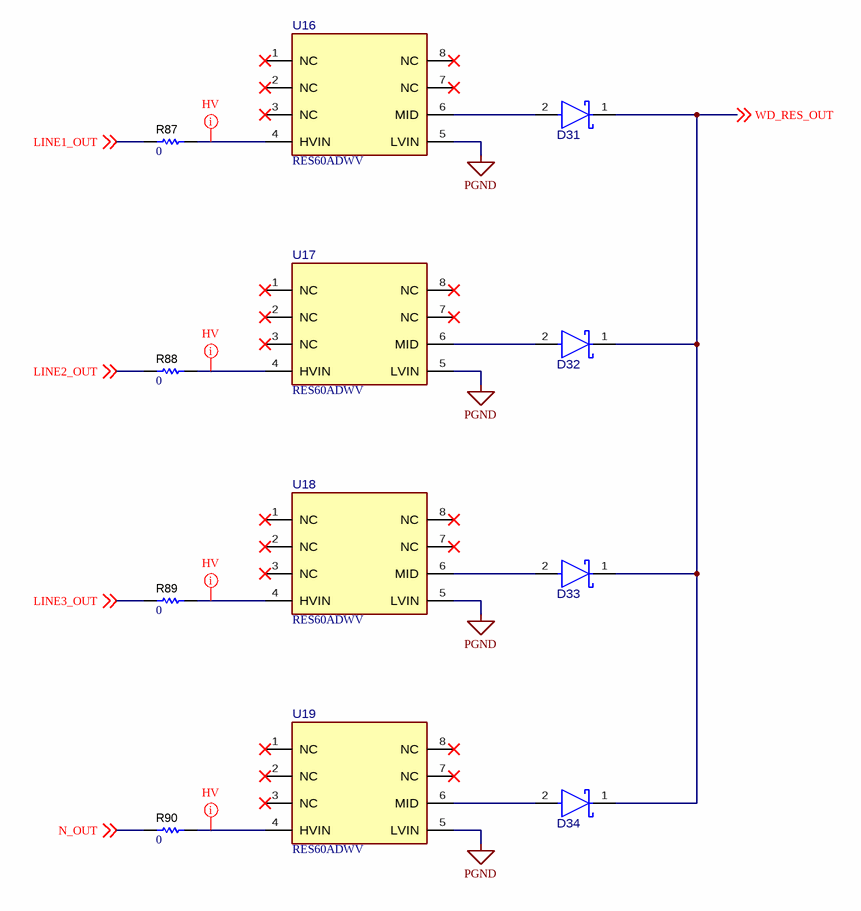
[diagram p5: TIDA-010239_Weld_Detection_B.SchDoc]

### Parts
D31  GSRB751S-40  [FP-GSRB751S-40_SOD523-0]  (value not drawn)
D32  GSRB751S-40  [FP-GSRB751S-40_SOD523-0]  (value not drawn)
D33  GSRB751S-40  [FP-GSRB751S-40_SOD523-0]  (value not drawn)
D34  GSRB751S-40  [FP-GSRB751S-40_SOD523-0]  (value not drawn)
R87  ValueDisplayed: 0  [1206]  (hidden comment: RC1206JR-070RL)
R88  ValueDisplayed: 0  [1206]  (hidden comment: RC1206JR-070RL)
R89  ValueDisplayed: 0  [1206]  (hidden comment: RC1206JR-070RL)
R90  ValueDisplayed: 0  [1206]  (hidden comment: RC1206JR-070RL)
U16  RES60ADWV  [DWV0008A-MFG]
U17  RES60ADWV  [DWV0008A-MFG]
U18  RES60ADWV  [DWV0008A-MFG]
U19  RES60ADWV  [DWV0008A-MFG]

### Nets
PGND: U16.5(LVIN) U17.5(LVIN) U18.5(LVIN) U19.5(LVIN)
LINE1_OUT: R87.2 ; off-sheet LINE1_OUT
LINE2_OUT: R88.2 ; off-sheet LINE2_OUT
LINE3_OUT: R89.2 ; off-sheet LINE3_OUT
N_OUT: R90.2 ; off-sheet N_OUT
WD_RES_OUT: D31.1(CATHODE) D32.1(CATHODE) D33.1(CATHODE) D34.1(CATHODE) ; off-sheet WD_RES_OUT
NetD31_2: D31.2(ANODE) U16.6(MID)
NetD32_2: D32.2(ANODE) U17.6(MID)
NetD33_2: D33.2(ANODE) U18.6(MID)
NetD34_2: D34.2(ANODE) U19.6(MID)
NetR87_1: R87.1 U16.4(HVIN)
NetR88_1: R88.1 U17.4(HVIN)
NetR89_1: R89.1 U18.4(HVIN)
NetR90_1: R90.1 U19.4(HVIN)

Not connected (* = marked no-connect by the designer): U16 1(NC)* 2(NC)* 3(NC)* 7(NC)* 8(NC)*; U17 1(NC)* 2(NC)* 3(NC)* 7(NC)* 8(NC)*; U18 1(NC)* 2(NC)* 3(NC)* 7(NC)* 8(NC)*; U19 1(NC)* 2(NC)* 3(NC)* 7(NC)* 8(NC)*

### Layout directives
net class HV: NetR87_1, NetR88_1, NetR89_1, NetR90_1

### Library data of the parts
D31-D34 = CMP-0120115-1: as D22 on sheet TIDA-010239_Weld_Detection
R87-R90 = CMP-0018759-2: as R59-R62 on sheet TIDA-010239_Relay_DRV
U16-U19 = CMP-0121043-1: Manufacturer: Texas Instruments; SizeZ_mm: 2.8mm; AEC Qualified: No; Standoff Height: 0.36mm

## Sheet TIDA-010239_HPGP_ZC.SchDoc
size 431 x 279 mm; Date: Not shown in title block; ApprovedBy: Not shown in title block; CheckedBy: Not shown in title block; Author: Not shown in title block; CompanyName: Not shown in title block; Engineer: Not shown in title block; Organization: Not shown in title block; Address1: Not shown in title block; Address2: Not shown in title block; Address3: Not shown in title block; Address4: Not shown in title block; DocumentNumber: 1; Revision: Use project parameter SCH_Rev; SheetNumber: 7; SheetTotal: 9; PageSetup: Record=PageOptions¦CenterHorizontal=True¦CenterVertical=True¦PrintScale=1.00¦XCorrection=1.00¦YCorrection=1.00¦PrintKind=0¦BorderSize=5000000¦LeftOffset=0¦BottomOffset=0¦Orientation=2¦PaperLength=1000¦PaperWidth=1000¦Scale=100¦PaperSource=15¦PrintQuality=600¦MediaType=1¦DitherType=10¦PaperKind=Letter¦PrintScaleMode=1
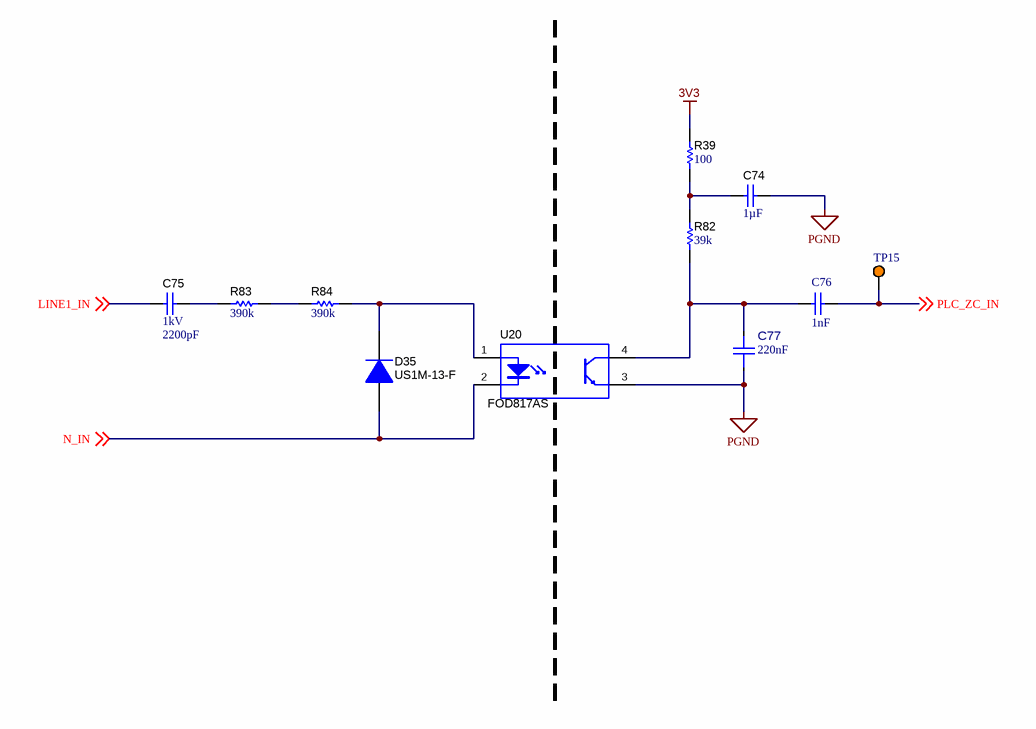
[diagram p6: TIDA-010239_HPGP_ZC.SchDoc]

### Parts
C74  Cap_F: 1µF  [0603]  (hidden comment: GCM188R71E105KA64D)
C75  VDC_V: 1kV  ValueDisplayed: 2200pF  [1206]  (hidden comment: GRM31BR73A222KW01L)
C76  value 1nF  [WCAP-CSGP_0603_L1.6W0.8H0.8_Reflow]  (hidden comment: 885012206083)
C77  Cap_F: 220nF  [FP-CC0603KRX7R7BB224_0603-MFG]  (hidden comment: CC0603KRX7R7BB224)
D35  US1M-13-F  [SMA]
R39  ValueDisplayed: 100  [0603]  (hidden comment: CRCW0603100RJNEA)
R82  ValueDisplayed: 39k  [0603]  (hidden comment: RC0603JR-0739KL)
R83  ValueDisplayed: 390k  [1206]  (hidden comment: CRCW1206390KJNEA)
R84  ValueDisplayed: 390k  [1206]  (hidden comment: CRCW1206390KJNEA)
TP15  5003  [Keystone5003]  (value not drawn)
U20  FOD817AS  [N04C]

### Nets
3V3: R39.2
PGND: C74.2 C77.1 U20.3(E)
LINE1_IN: C75.2 ; off-sheet LINE1_IN
N_IN: D35.2(A) U20.2(K) ; off-sheet N_IN
PLC_ZC_IN: C76.2 TP15.1 ; off-sheet PLC_ZC_IN
NetC74_1: C74.1 R39.1 R82.2
NetC75_1: C75.1 R83.2
NetC76_1: C76.1 C77.2 R82.1 U20.4(C)
NetD35_1: D35.1(K) R84.1 U20.1(A)
NetR83_1: R83.1 R84.2

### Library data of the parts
C74 = CMP-0007139-4: CAP, CERM, 1 uF, 25 V, +/- 10%, X7R, AEC-Q200 Grade 1, 0603; Manufacturer: MuRata; TaMin_C: -55°C; Polarized: N; SizeAreaWB_mm2: 4.68; Value1: Unknown; U/M: EA; Value: 1uF; TaMax_C: 125°C; SizeZ_mm: 1; SizeX_mm: 1.6; SizeY_mm: 0.8; Value2: 25V; SizeArea_mm2: 1.28; AEC Qualified: Y; AEC Category: Q200
C75 = CMP-0008918-2: CAP, CERM, 2200 pF, 1000 V, +/- 10%, X7R, 1206; Manufacturer: MuRata; TaMin_C: -55°C; Polarized: N; SizeAreaWB_mm2: 10.92; Value1: Unknown; U/M: EA; Value: 2200pF; TaMax_C: 125°C; SizeZ_mm: 1.35; SizeX_mm: 3.2; SizeY_mm: 1.6; Value2: 1000V; SizeArea_mm2: 5.12; Cap_F: 2.2nF; AEC Category: Q200
C76 = CMP-0108297-1: WCAP-CSGP Multilayer Ceramic Chip Capacitor, General Purpose, size 0603, X7R, 1nF, 50VDC; Manufacturer: Wurth Elektronik; Capacitance Tolerance: +/-10%; Dissipation Factor: 2.5%; Insulation Resistance: 10GOhm; Rated Voltage (DC): 50V; Technical Reference: X7R0603102K050DFCT10000
C77 = CMP-0091480-1: 0603 0.22 uF 16 V ±10 % Tolerance X7R SMT Multilayer Ceramic Capacitor; Manufacturer: Yageo; VDC_V: 16V; TempCo: 15%; AEC Qualified: No; Tolerance_%: 10%; Value: 220nF; SizeZ_mm: 0.9mm
D35 = CMP-0076882-2: Diode, Ultrafast, 1000 V, 1 A, SMA; Manufacturer: Diodes Inc.; SizeAreaWB_mm2: 37.3428; Vr_V: 1kV; SizeArea_mm2: 16.3228; TJmax_C: 150°C; AEC Category: Q101; Value: 1000V; SizeZ_mm: 2.87; Green_REACh: Incomplete; Io_A: 1A; Vf_V: 1.7V; SizeY_mm: 2.92; Green_Lifecycle: Not Set; SizeX_mm: 5.59; RJC_CperW: 30.0
R39 = CMP-0025700-4: RES, 100, 5%, 0.1 W, AEC-Q200 Grade 0, 0603; Manufacturer: Vishay-Dale; Power_W: 100mW; TempCo: 200 ppm/C; Value_Code: 100R; Value: 100; EIA_Code: E24; SizeX_mm: 1.6; SizeY_mm: 0.8; SizeZ_mm: 1; Value2: 0.1W; SizeArea_mm2: 1.28; AEC Qualified: Y; VDC_V: 75V; AEC Category: Q200; AEC Grade: 0
R82 = CMP-0025917-5: RES, 39 k, 5%, 0.1 W, 0603; Manufacturer: Yageo; Power_W: 100mW; TempCo: 100 ppm/C; Value_Code: 39k0; Value: 39k; EIA_Code: E24; SizeX_mm: 1.6; SizeY_mm: 0.8; SizeZ_mm: 1; Value2: 0.1W; SizeArea_mm2: 1.28; AEC Qualified: N; VDC_V: 75V; AEC Category: Q200; SizeAreaWB_mm2: 4.68
R83 R84 = CMP-0018664-3: RES, 390 k, 5%, 0.25 W, AEC-Q200 Grade 0, 1206; Manufacturer: Vishay-Dale; Power_W: 250mW; TempCo: 200 ppm/C; Value: 390k; EIA_Code: E24; SizeX_mm: 3.2; SizeY_mm: 1.6; SizeZ_mm: 1.35; Value2: 0.25W; SizeArea_mm2: 5.12; AEC Qualified: Y; VDC_V: 200V; AEC Category: Q200; AEC Grade: 0
TP15 = CMP-0055140-2: as TP12-TP14 on sheet TIDA-010239_Relay_DRV
U20 = CMP-0006177-3: Optocoupler, 5 kV, 80-160% CTR, SMT; Manufacturer: Fairchild Semiconductor; CTR (Max): 160%; CTR (Min): 80%; Voltage_Isolation_Vrms: 5kV

## Sheet TIDA-010239_Connector.SchDoc
size 431 x 279 mm; Date: Not shown in title block; ApprovedBy: Not shown in title block; CheckedBy: Not shown in title block; Author: Not shown in title block; CompanyName: Not shown in title block; Engineer: Not shown in title block; Organization: Not shown in title block; Address1: Not shown in title block; Address2: Not shown in title block; Address3: Not shown in title block; Address4: Not shown in title block; DocumentNumber: 1; Revision: Use project parameter SCH_Rev; SheetNumber: 8; SheetTotal: 9; PageSetup: Record=PageOptions¦CenterHorizontal=True¦CenterVertical=True¦PrintScale=1.00¦XCorrection=1.00¦YCorrection=1.00¦PrintKind=0¦BorderSize=5000000¦LeftOffset=0¦BottomOffset=0¦Orientation=2¦PaperLength=1000¦PaperWidth=1000¦Scale=100¦PaperSource=15¦PrintQuality=600¦MediaType=1¦DitherType=10¦PaperKind=Letter¦PrintScaleMode=1
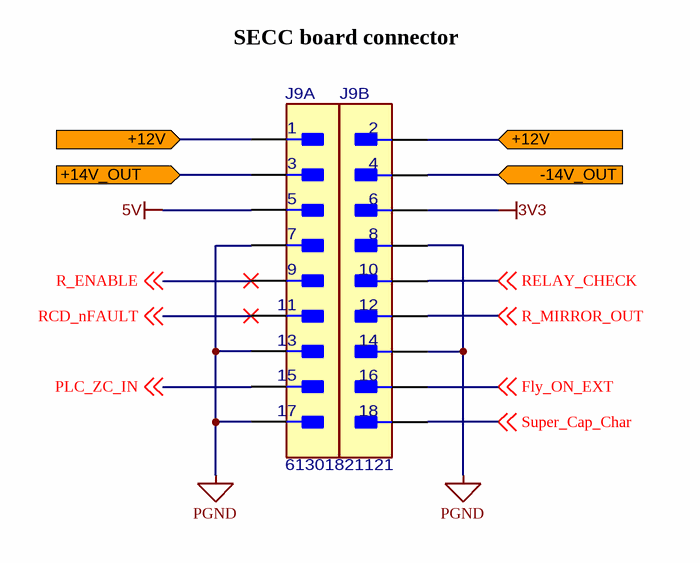
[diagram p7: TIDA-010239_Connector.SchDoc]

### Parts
J9  61301821121  [FP-61301821121_HDR18-MFG]  (parts A,B of 2)

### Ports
+12V (in), +14V_OUT (in), -14V_OUT (in)

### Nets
3V3: J9.6
5V: J9.5
PGND: J9.7 J9.8 J9.13 J9.14 J9.17
+12V: J9.1 J9.2 ; port +12V
+14V_OUT: J9.3 ; port +14V_OUT
-14V_OUT: J9.4 ; port -14V_OUT
Fly_ON_EXT: J9.16 ; off-sheet Fly_ON_EXT
PLC_ZC_IN: J9.15 ; off-sheet PLC_ZC_IN
R_ENABLE: J9.9 ; off-sheet R_ENABLE
R_MIRROR_OUT: J9.12 ; off-sheet R_MIRROR_OUT
RCD_nFAULT: J9.11 ; off-sheet RCD_nFAULT
RELAY_CHECK: J9.10 ; off-sheet RELAY_CHECK
Super_Cap_Char: J9.18 ; off-sheet Super_Cap_Char

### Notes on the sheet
- SECC board connector

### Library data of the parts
J9 = CMP-0124771-1: Connector Header Through Hole 18 position 0.100" (2.54mm); Manufacturer: Wurth; ContactFinish: Gold; Current_A: 3A; Row_Count: 2; Voltage_V: 250V; AEC Qualified: No; Conn Gender: Male; Conn Orientation: Vertical; SizeZ_mm: 8.89mm

## Sheet TIDA-010239_Hardware.SchDoc
size 431 x 279 mm; Date: Not shown in title block; ApprovedBy: Not shown in title block; CheckedBy: Not shown in title block; Author: Not shown in title block; CompanyName: Not shown in title block; Engineer: Not shown in title block; Organization: Not shown in title block; Address1: Not shown in title block; Address2: Not shown in title block; Address3: Not shown in title block; Address4: Not shown in title block; DocumentNumber: 3; Revision: Use project parameter SCH_Rev; SheetNumber: 9; SheetTotal: 9; PageSetup: Record=PageOptions¦CenterHorizontal=True¦CenterVertical=True¦PrintScale=1.00¦XCorrection=1.00¦YCorrection=1.00¦PrintKind=0¦BorderSize=5000000¦LeftOffset=0¦BottomOffset=0¦Orientation=2¦PaperLength=1000¦PaperWidth=1000¦Scale=100¦PaperSource=15¦PrintQuality=600¦MediaType=1¦DitherType=10¦PaperKind=Letter¦PrintScaleMode=1
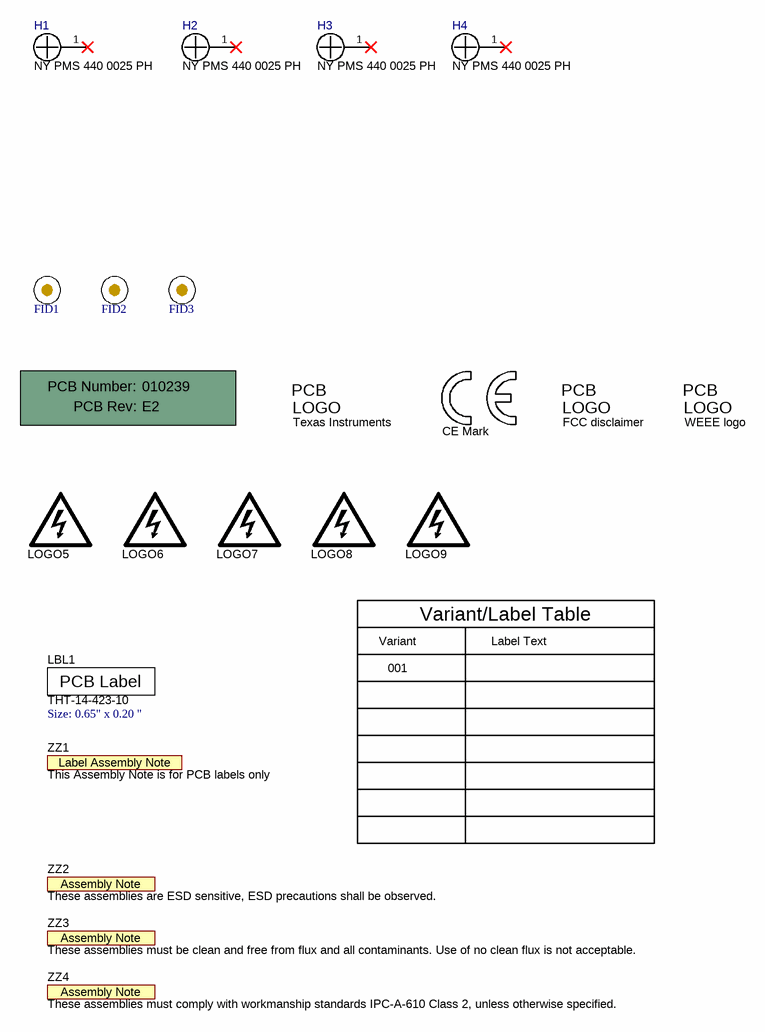
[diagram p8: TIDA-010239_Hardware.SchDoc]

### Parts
!PCB1  Printed Circuit Board  (value not drawn)  (mechanical)
FID1  Fiducial  [Fiducial10-20]  (value not drawn)
FID2  Fiducial  [Fiducial10-20]  (value not drawn)
FID3  Fiducial  [Fiducial10-20]  (value not drawn)
H1  NY PMS 440 0025 PH  [NY PMS 440 0025 PH]
H2  NY PMS 440 0025 PH  [NY PMS 440 0025 PH]
H3  NY PMS 440 0025 PH  [NY PMS 440 0025 PH]
H4  NY PMS 440 0025 PH  [NY PMS 440 0025 PH]
LBL1  THT-14-423-10  Note: Size: 0.65" x 0.20 "  [Label_650x200]
Logo1  CE Mark  [CE_Mark_5mm]  (no BOM)
Logo2  Texas Instruments  [TI_Stacked_Overlay_Small]  (no BOM)
Logo3  FCC disclaimer  [FCC_disclaimer]  (no BOM)
Logo4  WEEE logo  [WEEE_Minimum]  (no BOM)
LOGO5  DANGER HIGH VOLTAGE  [IEC_HighVoltage_Medium]  (value not drawn)  (no BOM)
LOGO6  DANGER HIGH VOLTAGE  [IEC_HighVoltage_Medium]  (value not drawn)  (no BOM)
LOGO7  DANGER HIGH VOLTAGE  [IEC_HighVoltage_Medium]  (value not drawn)  (no BOM)
LOGO8  DANGER HIGH VOLTAGE  [IEC_HighVoltage_Medium]  (value not drawn)  (no BOM)
LOGO9  DANGER HIGH VOLTAGE  [IEC_HighVoltage_Medium]  (value not drawn)  (no BOM)
ZZ1  This Assembly Note is for PCB labels only  [AssemblyNoteLabel]  (no BOM)
ZZ2  These assemblies are ESD sensitive, ESD precautions shall be observed.  [AssemblyNote]  (no BOM)
ZZ3  These assemblies must be clean and free from flux and all contaminants. Use of no clean flux is not acceptable.  [AssemblyNote]  (no BOM)
ZZ4  These assemblies must comply with workmanship standards IPC-A-610 Class 2, unless otherwise specified.  [AssemblyNote]  (no BOM)

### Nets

Not connected (* = marked no-connect by the designer): H1 1*; H2 1*; H3 1*; H4 1*

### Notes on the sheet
- Variant
- Variant/Label Table
- Label Text
- 001

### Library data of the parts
!PCB1 = CMP-0003618-2: Manufacturer: Any; PartNumber: 010239
FID1-FID3 = CMP-0077181-1: Fiducial mark.  There is nothing to buy or mount.
H1-H4 = CMP-0003617-1: Machine Screw, Round, #4-40 x 1/4, Nylon, Philips panhead; Manufacturer: B&F Fastener Supply; CompType: Hardware
LBL1 = CMP-0003625-1: Thermal Transfer Printable Labels, 0.650" W x 0.200" H - 10,000 per roll; Manufacturer: Brady
Logo1 = CMP-0074844-2: Manufacturer: Texas Instruments; SymbolCreator: a0412235; AEC Category: Q200; CompType: IC
Logo2 = CMP-0074838-1: Texas Instrument Corporate Signature; SymbolCreator: a0412235; Lib Reference: TI_Logo
Logo3 = CMP-0074847-1: FCC_disclaimer
Logo4 = CMP-0074769-4: Manufacturer: Texas Instruments; CompType: IC; AEC Category: Q200
LOGO5-LOGO9 = CMP-0074835-1: IEC 61010-1 High Voltage Warning; SymbolCreator: a0412235; Lib Reference: IEC_HighVoltage
ZZ1 = CMP-0003616-3
ZZ2 = CMP-0077236-1
ZZ3 = CMP-0077237-1
ZZ4 = CMP-0077238-1

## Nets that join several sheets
3V3: TIDA-010239_Relay_DRV (5 pins), TIDA-010239_Weld_Detection (R69.2 R78.2 R85.2), TIDA-010239_HPGP_ZC (R39.2), TIDA-010239_Connector (J9.6)
5V: TIDA-010239_Weld_Detection (C64.1 U11.5), TIDA-010239_Connector (J9.5)
12V: TIDA-010239_PWR_Flyback (13 pins), TIDA-010239_Relay_DRV (F4.2)
PGND: TIDA-010239_PWR_Flyback (23 pins), TIDA-010239_PWR_Backup (23 pins), TIDA-010239_Relay_DRV (12 pins), TIDA-010239_Weld_Detection (25 pins), TIDA-010239_Weld_Detection_B (U16.5 U17.5 U18.5 U19.5), TIDA-010239_HPGP_ZC (C74.2 C77.1 U20.3), TIDA-010239_Connector (5 pins)
+12V: TIDA-010239_PWR_Flyback (R14.2), TIDA-010239_PWR_Backup (5 pins), TIDA-010239_Connector (J9.1 J9.2)
+14V_OUT: TIDA-010239_PWR_Flyback (D2.1), TIDA-010239_Connector (J9.3)
+14V_SW: TIDA-010239_PWR_Flyback (D1.2 R1.1 T1.14), TIDA-010239_PWR_Backup (D14.2 D16.2)
-14V_OUT: TIDA-010239_PWR_Flyback (D6.2), TIDA-010239_Connector (J9.4)
Fly_ON_EXT: TIDA-010239_PWR_Backup (Q3.3), TIDA-010239_Connector (J9.16)
LINE1_IN: TIDA-010239_PWR_Flyback (F1.2 TP1.1), TIDA-010239_Relay_DRV (C54.1 J1.1 K1.6), TIDA-010239_HPGP_ZC (C75.2)
LINE1_OUT: TIDA-010239_Relay_DRV (J2.1 K1.5), TIDA-010239_Weld_Detection (C62.1), TIDA-010239_Weld_Detection_B (R87.2)
LINE2_IN: TIDA-010239_PWR_Flyback (F2.2 TP2.1), TIDA-010239_Relay_DRV (C55.1 J3.1 K1.7)
LINE2_OUT: TIDA-010239_Relay_DRV (J4.1 K1.4), TIDA-010239_Weld_Detection (C65.1), TIDA-010239_Weld_Detection_B (R88.2)
LINE3_IN: TIDA-010239_PWR_Flyback (F3.2 TP3.1), TIDA-010239_Relay_DRV (C56.1 J5.1 K1.8)
LINE3_OUT: TIDA-010239_Relay_DRV (J6.1 K1.3), TIDA-010239_Weld_Detection (C69.1), TIDA-010239_Weld_Detection_B (R89.2)
N_IN: TIDA-010239_PWR_Flyback (8 pins), TIDA-010239_Relay_DRV (6 pins), TIDA-010239_HPGP_ZC (D35.2 U20.2)
N_OUT: TIDA-010239_Relay_DRV (J8.1 K1.2), TIDA-010239_Weld_Detection (C71.1), TIDA-010239_Weld_Detection_B (R90.2)
PLC_ZC_IN: TIDA-010239_HPGP_ZC (C76.2 TP15.1), TIDA-010239_Connector (J9.15)
R_ENABLE: TIDA-010239_Relay_DRV (R66.2 U9.2), TIDA-010239_Connector (J9.9)
R_MIRROR_OUT: TIDA-010239_Relay_DRV (K1.12 R58.1 TP12.1), TIDA-010239_Connector (J9.12)
RCD_nFAULT: TIDA-010239_Relay_DRV (R92.1 U9.1), TIDA-010239_Connector (J9.11)
RELAY_CHECK: TIDA-010239_Weld_Detection (5 pins), TIDA-010239_Connector (J9.10)
Super_Cap_Char: TIDA-010239_PWR_Backup (TP10.1 U5.5), TIDA-010239_Connector (J9.18)
WD_RES_OUT: TIDA-010239_Weld_Detection (R74.1), TIDA-010239_Weld_Detection_B (D31.1 D32.1 D33.1 D34.1)

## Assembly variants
001: not fitted D31 D32 D33 D34 L7 R74 R76 R87 R88 R89 R90 U16 U17 U18 U19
